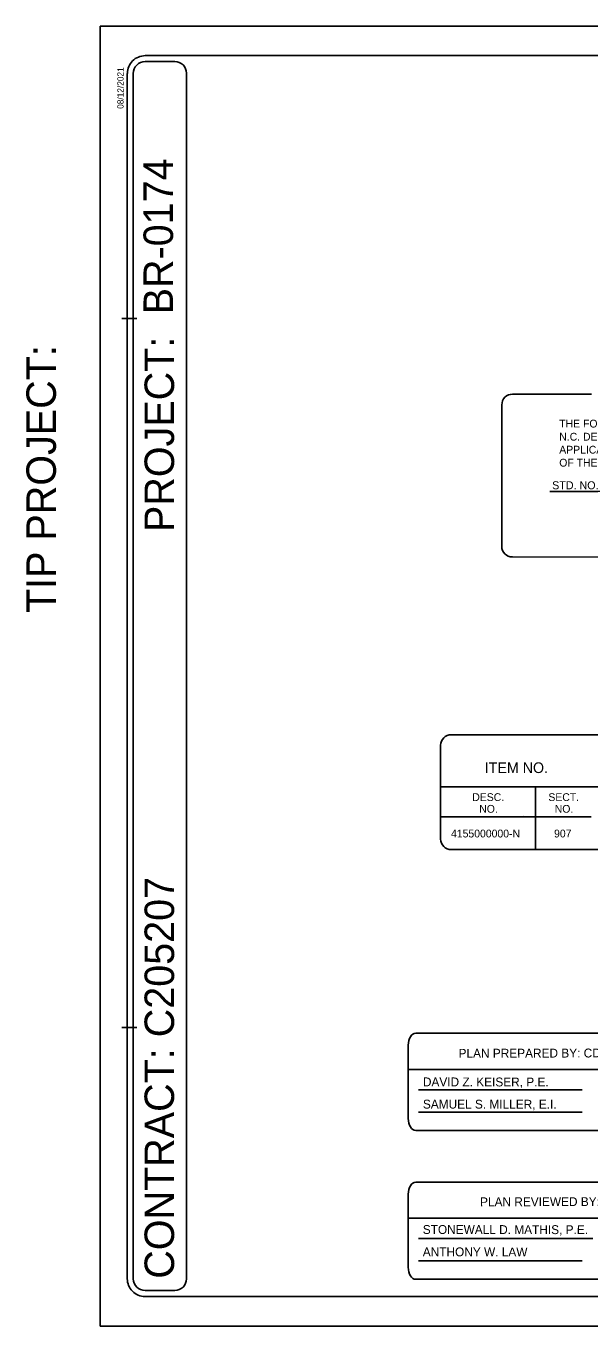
# Model space of a CAD drawing. Extents: x -2362 to 1945, y 0 to 1100.
# Drawn here: x -63 to 414, y 0 to 1100 of the extents above; entities that cross this region are included whole.
import ezdxf

# ---------------------------------------------------------------- set-up
doc = ezdxf.new("R2010")
doc.units = 0
for name, color, linetype in [('Default', 7, 'Continuous'), ('Exist Utilities Telephone Test Hole SUE LOS A CELL', 7, 'Continuous'), ('Sheet_Plan_CELL', 7, 'Continuous'), ('Sheet_Title_Block_Text', 7, 'Continuous'), ('z - Construction', 7, 'Continuous')]:
    doc.layers.add(name, color=color, linetype=linetype)

msp = doc.modelspace()

# ---------------------------------------------------------------- linework, layer by layer
at = {"layer": 'Default'}
msp.add_line((358.1, 431.8), (358.1, 431.8), dxfattribs=at)
at = {"layer": 'Exist Utilities Telephone Test Hole SUE LOS A CELL'}
for p, q in [((0, 1100), (1700, 1100)), ((0, 0), (0, 1100)), ((0, 0), (1700, 0))]:
    msp.add_line(p, q, dxfattribs=at)
at = {"layer": 'Sheet_Plan_CELL'}
msp.add_line((0, 0), (0, 0), dxfattribs=at)
at = {"layer": 'z - Construction'}
for p, q in [((38.1, 1074.9), (1652, 1074.9)), ((23, 1059.9), (23, 40)), ((28.1, 40), (28.1, 1059.9)), ((73.1, 40), (73.1, 1060)), ((18.5, 852.5), (31, 852.5)), ((18.5, 852.5), (31, 852.5)), ((349.1, 788.4), (415.9, 788.4)), ((339.9, 659.8), (340, 779.4)), ((380.7, 706.1), (430, 706.1)), ((349, 650.7), (827.4, 650.5)), ((297.1, 500.3), (451.6, 500.3)), ((288.1, 412), (288.2, 491.4)), ((288.2, 456.3), (774.8, 456.3)), ((368.4, 403.1), (368.4, 456.3)), ((288.2, 430.7), (415.7, 430.7)), ((297.1, 403.1), (848.6, 403.1)), ((18.5, 252.5), (31, 252.5)), ((18.5, 252.5), (31, 252.5)), ((267.2, 247.7), (765.1, 247.7)), ((260.8, 175.7), (260.8, 237.5)), ((260.8, 217.1), (558.9, 217)), ((269.6, 199.8), (408, 199.8)), ((269.6, 180.9), (408, 180.9)), ((765, 165.4), (267.2, 165.4)), ((267.2, 121.7), (710, 121.7)), ((260.8, 49.7), (260.8, 111.5)), ((260.8, 91.3), (716.4, 91.3)), ((269.5, 74.1), (416.9, 74.1)), ((269.5, 55.2), (407.9, 55.2)), ((269.5, 55.2), (407.9, 55.2)), ((269.5, 55.2), (407.9, 55.2)), ((710, 39.5), (267.2, 39.5)), ((38.1, 29.9), (63, 29.9)), ((38.1, 25), (1652, 25))]:
    msp.add_line(p, q, dxfattribs=at)
msp.add_lwpolyline([(63, 1069.9), (38.1, 1069.9)], dxfattribs=at)
for centre, radius, start, end in [((38.1, 1059.9), 15, 89.9714, 180), ((38.1, 1059.9), 10, 89.9714, 180), ((63.1, 1060), 10, 0, 90), ((349.1, 779.4), 9.09, 89.9734, 179.9734), ((349, 659.8), 9.09, 179.9734, 269.9734), ((297.1, 491.4), 8.91, 89.9734, 179.9734), ((297.1, 412), 8.91, 179.9734, 269.9734), ((38, 40), 15, 180.0932, 270.0932), ((38.1, 40), 10, 180, 270), ((63.1, 40), 10, 270, 360)]:
    msp.add_arc(centre, radius, start, end, dxfattribs=at)
for centre, major_axis, start_param, end_param in [((267.2, 237.5), (0, 10.2), 0.000702, 1.571498), ((267.2, 175.7), (0, -10.2), 4.713091, 6.283887), ((267.2, 111.5), (0, 10.2), 0.000687, 1.567869), ((267.2, 49.7), (0, -10.2), 4.713091, 6.283872)]:
    msp.add_ellipse(centre, major_axis=major_axis, ratio=0.62659, start_param=start_param, end_param=end_param, dxfattribs=at)

# ---------------------------------------------------------------- texts
at = {"layer": 'Sheet_Plan_CELL'}
for s, height, rotation, p in [('THE FOLLOWING ROADWAY STANDARDS AS APPEAR IN "ROADWAY STANDARD DRAWINGS" - ', 6.6, 359.9332, (388.6, 760.3)), ('N.C. DEPARTMENT OF TRANSPORTATION - RALEIGH, N.C., DATED JANUARY 2024 ARE', 6.6, 359.9332, (388.6, 749.2)), ('APPLICABLE TO THIS PROJECT AND BY REFERENCE HEREBY ARE CONSIDERED A PART', 6.6, 359.9332, (388.6, 738.2)), ('OF THESE PLANS:', 6.6, 359.9332, (388.6, 727.2)), ('STD. NO.', 6.77, 359.9734, (382.6, 708)), ('DAVID Z. KEISER, P.E.', 7.5, 359.9372, (273.2, 202.8)), ('SAMUEL S. MILLER, E.I.', 7.5, 359.9372, (273.2, 184)), ('STONEWALL D. MATHIS, P.E.', 7.5, 359.9372, (273.1, 77.9)), ('ANTHONY W. LAW', 7.5, 359.9372, (273.1, 59))]:
    msp.add_text(s, height=height, rotation=rotation, dxfattribs=at).set_placement(p)
for s, height, p in [('ITEM NO.', 9, (325.6, 467.9)), ('DESC.', 6.6, (315, 444.2)), ('NO.', 6.6, (320.9, 434.3)), ('SECT.', 6.6, (379.4, 444.2)), ('NO.', 6.6, (384.8, 434.3)), ('4155000000-N', 6.6, (297, 413.4)), ('907', 6.6, (384.2, 413.4))]:
    msp.add_text(s, height=height, dxfattribs=at).set_placement(p)
at = {"layer": 'Sheet_Title_Block_Text'}
for s, p in [('PLAN PREPARED BY: CDM SMITH, INC.', (303.4, 227)), ('PLAN REVIEWED BY: N.C.D.O.T. DIVISION 3', (321.6, 101.3))]:
    msp.add_text(s, height=7.5, rotation=0.1194, dxfattribs=at).set_placement(p)
at = {"layer": 'z - Construction'}
for s, height, p in [('08/12/2021', 5.25, (19.8, 1029.9)), ('BR-0174', 25, (61.7, 856)), ('TIP PROJECT:', 25, (-37.4, 603.3)), ('PROJECT:', 25, (62.6, 671.8)), ('CONTRACT: C205207', 25, (62.6, 40))]:
    msp.add_text(s, height=height, rotation=90, dxfattribs=at).set_placement(p)

doc.saveas('drawing.dxf')
